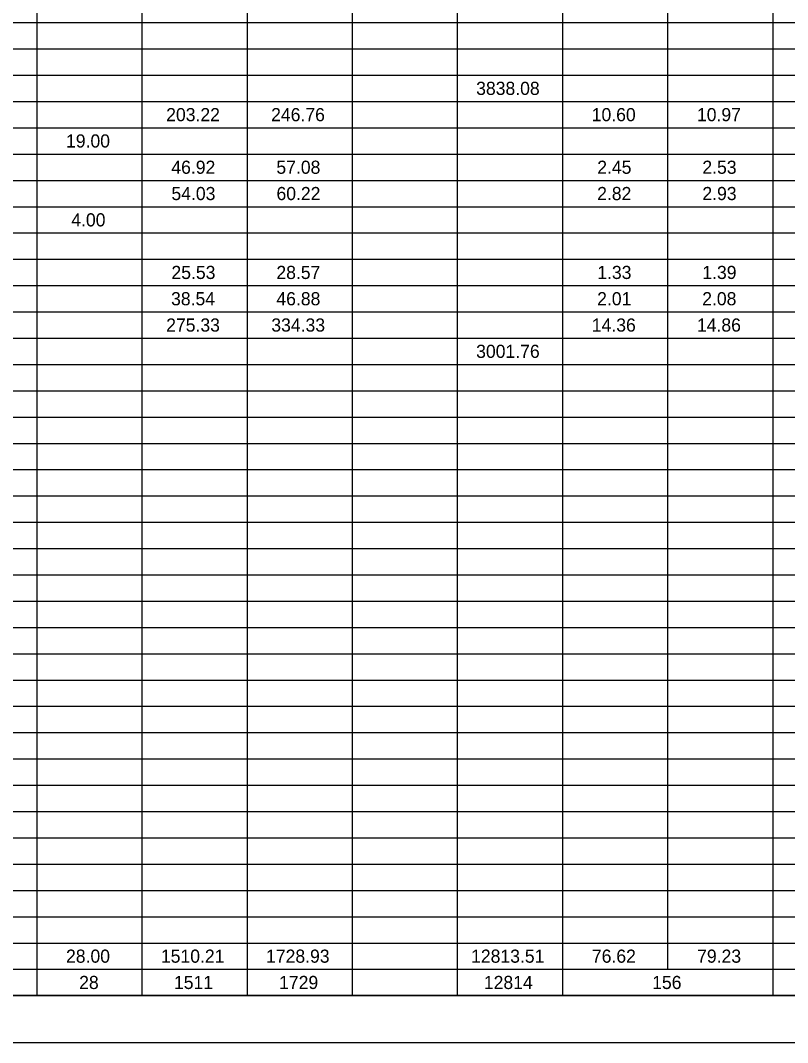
# Model space of a CAD drawing. Extents: x 0 to 34, y 0 to 22.
# Drawn here: x 17.24 to 25.41, y 0 to 10.88 of the extents above; entities that cross this region are included whole.
import ezdxf

# ---------------------------------------------------------------- set-up
doc = ezdxf.new("R2010")
doc.units = 0
for name, color, linetype in [('SH_Border', 7, 'Continuous'), ('SH_Cut_Line', 7, 'Continuous'), ('SH_Data', 7, 'Continuous'), ('SH_Text', 7, 'Continuous')]:
    doc.layers.add(name, color=color, linetype=linetype)

msp = doc.modelspace()

# ---------------------------------------------------------------- linework, layer by layer
at = {"layer": 'SH_Border'}
msp.add_lwpolyline([(1.5, 21.5), (33.5, 21.5), (33.5, 0.5), (1.5, 0.5)], close=True, dxfattribs=at)
at = {"layer": 'SH_Cut_Line'}
msp.add_lwpolyline([(0, 0), (34, 0), (34, 22), (0, 22)], close=True, dxfattribs=at)
at = {"layer": 'SH_Data'}
for p, q in [((17.411, 21.5), (17.411, 0.5)), ((18.531, 21.5), (18.531, 0.5)), ((19.651, 21.5), (19.651, 0.5)), ((20.771, 21.5), (20.771, 0.5)), ((21.891, 21.5), (21.891, 0.5)), ((23.011, 21.5), (23.011, 0.5)), ((24.131, 21.5), (24.131, 0.78)), ((25.251, 21.5), (25.251, 0.5)), ((1.5, 10.86), (31.971, 10.86)), ((1.5, 10.58), (31.971, 10.58)), ((1.5, 10.3), (31.971, 10.3)), ((1.5, 10.02), (31.971, 10.02)), ((1.5, 9.74), (31.971, 9.74)), ((1.5, 9.46), (31.971, 9.46)), ((1.5, 9.18), (31.971, 9.18)), ((1.5, 8.9), (31.971, 8.9)), ((1.5, 8.62), (31.971, 8.62)), ((1.5, 8.34), (31.971, 8.34)), ((1.5, 8.06), (31.971, 8.06)), ((1.5, 7.78), (31.971, 7.78)), ((1.5, 7.5), (31.971, 7.5)), ((1.5, 7.22), (31.971, 7.22)), ((1.5, 6.94), (31.971, 6.94)), ((1.5, 6.66), (31.971, 6.66)), ((1.5, 6.38), (31.971, 6.38)), ((1.5, 6.1), (31.971, 6.1)), ((1.5, 5.82), (31.971, 5.82)), ((1.5, 5.54), (31.971, 5.54)), ((1.5, 5.26), (31.971, 5.26)), ((1.5, 4.98), (31.971, 4.98)), ((1.5, 4.7), (31.971, 4.7)), ((1.5, 4.42), (31.971, 4.42)), ((1.5, 4.14), (31.971, 4.14)), ((1.5, 3.86), (31.971, 3.86)), ((1.5, 3.58), (31.971, 3.58)), ((1.5, 3.3), (31.971, 3.3)), ((1.5, 3.02), (31.971, 3.02)), ((1.5, 2.74), (31.971, 2.74)), ((1.5, 2.46), (31.971, 2.46)), ((1.5, 2.18), (31.971, 2.18)), ((1.5, 1.9), (31.971, 1.9)), ((1.5, 1.62), (31.971, 1.62)), ((1.5, 1.34), (31.971, 1.34)), ((1.5, 1.06), (31.971, 1.06)), ((1.5, 0.78), (31.971, 0.78)), ((1.5, 0.5), (31.971, 0.5))]:
    msp.add_line(p, q, dxfattribs=at)

# ---------------------------------------------------------------- texts
at = {"layer": 'SH_Text'}
for s, p in [('3838.08', (22.092, 10.09)), ('203.22', (18.79, 9.81)), ('246.76', (19.908, 9.81)), ('10.60', (23.323, 9.81)), ('10.97', (24.444, 9.81)), ('19.00', (17.723, 9.53)), ('46.92', (18.845, 9.25)), ('57.08', (19.964, 9.25)), ('2.45', (23.382, 9.25)), ('2.53', (24.502, 9.25)), ('54.03', (18.846, 8.97)), ('60.22', (19.965, 8.97)), ('2.82', (23.381, 8.97)), ('2.93', (24.502, 8.97)), ('4.00', (17.779, 8.69)), ('25.53', (18.846, 8.13)), ('28.57', (19.964, 8.13)), ('1.33', (23.382, 8.13)), ('1.39', (24.501, 8.13)), ('38.54', (18.842, 7.85)), ('46.88', (19.964, 7.85)), ('2.01', (23.381, 7.85)), ('2.08', (24.5, 7.85)), ('275.33', (18.79, 7.57)), ('334.33', (19.91, 7.57)), ('14.36', (23.324, 7.57)), ('14.86', (24.444, 7.57)), ('3001.76', (22.092, 7.29)), ('28.00', (17.723, 0.85)), ('1510.21', (18.734, 0.85)), ('1728.93', (19.854, 0.85)), ('12813.51', (22.038, 0.85)), ('76.62', (23.325, 0.85)), ('79.23', (24.446, 0.85)), ('28', (17.863, 0.57)), ('1511', (18.873, 0.57)), ('1729', (19.993, 0.57)), ('12814', (22.174, 0.57)), ('156', (23.967, 0.57))]:
    msp.add_text(s, height=0.14, dxfattribs=at).set_placement(p)

doc.saveas('drawing.dxf')
